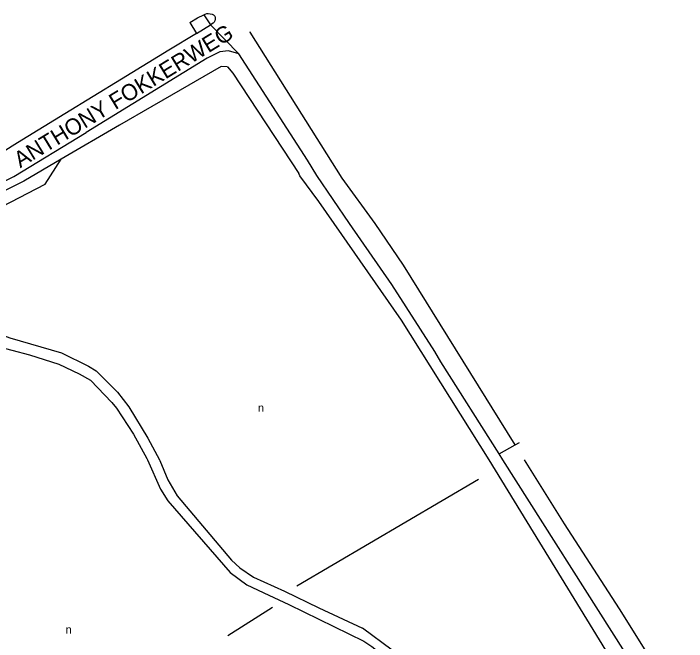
# Model space of a CAD drawing. Extents: x 158142 to 159655, y 385262 to 387204.
# Drawn here: x 158722.6 to 159056.3, y 386892.7 to 387204.1 of the extents above; entities that cross this region are included whole.
import ezdxf

# ---------------------------------------------------------------- set-up
doc = ezdxf.new("R2010")
doc.units = 0
for name, color, linetype in [('BLT_Basislijn', 7, 'Continuous'), ('BLT_Centroide', 7, 'Continuous'), ('BLT_Straatnaam_hoofdweg', 7, 'Continuous'), ('BLT_Vlakafsluiter', 7, 'Continuous')]:
    doc.layers.add(name, color=color, linetype=linetype)

msp = doc.modelspace()

# ---------------------------------------------------------------- linework, layer by layer
at = {"layer": 'BLT_Basislijn'}
for p, q in [((158816.98, 387203.45), (158820.21, 387198.39)), ((158810.01, 387199.61), (158813.28, 387194.17)), ((158813.28, 387194.17), (158820.21, 387198.39)), ((158796.72, 387161.14), (158791.2, 387157.97)), ((158747.97, 387154.24), (158724.65, 387139.9)), ((158863.12, 386920.32), (158953.18, 386973.15)), ((158828.89, 386895.71), (158851.1, 386909.64))]:
    msp.add_line(p, q, dxfattribs=at)
for points in [[(158810.01, 387199.61), (158813.77, 387201.92), (158816.98, 387203.45)], [(158816.98, 387203.45), (158817.67, 387203.77), (158818.39, 387204.08), (158819.17, 387204.08), (158821.12, 387203.68), (158821.81, 387203.39), (158822.38, 387202.81), (158822.65, 387202.12), (158822.65, 387201.31), (158822.44, 387200.42), (158822.11, 387199.72), (158821.57, 387199.19), (158820.21, 387198.39)], [(158813.28, 387194.17), (158799.69, 387185.88), (158776.2, 387171.42), (158747.97, 387154.24)], [(158971.41, 386990.24), (158916.01, 387079.26), (158902, 387100), (158885.59, 387122.48), (158840.02, 387194.82), (158840.05, 387195.16)], [(158834.41, 387184.11), (158829.27, 387185.49), (158824.86, 387185.13), (158818.64, 387181.87), (158758.56, 387145.1)], [(158963.45, 386985.65), (158934.46, 387031.39), (158931.54, 387036.42), (158910.12, 387069.72), (158889.28, 387100), (158873.07, 387123.67), (158868.42, 387131.41), (158834.41, 387184.11)], [(158828.56, 387177.67), (158825.65, 387177.76), (158796.72, 387161.14)], [(158828.56, 387177.67), (158828.76, 387177.61), (158831.4, 387174.54), (158864.09, 387124.71)], [(158791.2, 387157.97), (158775.15, 387148.76)], [(158775.15, 387148.76), (158746.24, 387131.78)], [(158656.08, 387088.12), (158665.09, 387093.2), (158682.14, 387102.8), (158697.48, 387110.9), (158722.77, 387123.25), (158758.56, 387145.1)], [(158724.65, 387139.9), (158717.53, 387135.44), (158691.44, 387119.47), (158680.62, 387110.78), (158678.6, 387109.21), (158673.07, 387105.98)], [(158601.87, 387043.7), (158663.51, 387076.57), (158703.82, 387101.71), (158706.29, 387105.85), (158716.99, 387108.3), (158738.31, 387119.52), (158746.24, 387131.78)], [(158746.24, 387131.78), (158727.74, 387120.92), (158711.33, 387112.82), (158635.07, 387069.15)], [(158958.42, 386982.75), (158915.05, 387052.06), (158881.53, 387100), (158873.95, 387110.89), (158864.56, 387123.63), (158864.09, 387124.71)], [(158689.96, 387059.86), (158690.74, 387056.94), (158693.14, 387055.45), (158700.11, 387051.72), (158707.9, 387047.99), (158720.81, 387043.24), (158746.32, 387035.84), (158759.77, 387029.16), (158763.61, 387026.95), (158774.11, 387016.37)], [(158685.14, 386982.75), (158687.96, 387003.81), (158689.75, 387042.71), (158690.33, 387044.22), (158691.93, 387045.94), (158693.02, 387046.57), (158696.92, 387046.72), (158702.97, 387043.35), (158712.86, 387039.5), (158730.6, 387034.84), (158745.14, 387030.27), (158755.08, 387025.45), (158760.74, 387022.19), (158771.37, 387011.13)], [(158774.11, 387016.37), (158779.72, 387009.05), (158789.26, 386993.54), (158794.96, 386982.75)], [(158771.37, 387011.13), (158773.61, 387008.33), (158782.1, 386995.45), (158788.78, 386983.36), (158789.05, 386982.75)], [(158965.29, 386982.75), (158963.45, 386985.65)], [(158789.05, 386982.75), (158795.46, 386968.16), (158799.18, 386962.38), (158830.05, 386926.87), (158838.27, 386920.81), (158849.21, 386915.61)], [(158794.96, 386982.75), (158795.14, 386982.41), (158799.16, 386972.86), (158803.82, 386964.96), (158830.77, 386933.07), (158834.86, 386929.24), (158841.64, 386924.58), (158857.01, 386917.58)], [(159103.65, 386742.39), (159099.94, 386748.36), (159098.83, 386750), (159091.4, 386761.9), (159082.06, 386777.82), (159078.59, 386786.94), (159064.74, 386809.3), (158958.42, 386982.75)], [(159083.22, 386795.27), (159074.66, 386809.4), (159063.45, 386827.49), (159040.75, 386863.13), (159025.87, 386887.16), (158965.29, 386982.75)], [(159089.59, 386802.28), (159073.79, 386827.75), (159023.04, 386908.93), (158995.81, 386951.04), (158976.07, 386982.75)], [(158849.21, 386915.61), (158859.17, 386910.94), (158896.27, 386892.92)], [(158857.01, 386917.58), (158873.93, 386909.3)], [(158873.93, 386909.3), (158895.73, 386899.33)], [(158929.94, 386871.18), (158915.21, 386884.4), (158910.37, 386888.39), (158895.73, 386899.33)], [(158896.27, 386892.92), (158900.34, 386890.22), (158909.81, 386882.69), (158919.27, 386874.47), (158929.05, 386864.56), (158932.64, 386858.61), (158944.48, 386824.01), (158945.66, 386818.41), (158945.43, 386809.38), (158943.15, 386802.81), (158940.34, 386797.93), (158934.04, 386791.34), (158913.14, 386778.2)]]:
    msp.add_lwpolyline(points, dxfattribs=at)
at = {"layer": 'BLT_Vlakafsluiter'}
for p, q in [((158820.21, 387198.39), (158834.41, 387184.11)), ((158963.45, 386985.65), (158971.41, 386990.24)), ((158971.41, 386990.24), (158973.44, 386991.41))]:
    msp.add_line(p, q, dxfattribs=at)

# ---------------------------------------------------------------- texts
at = {"layer": 'BLT_Centroide'}
for p in [(158843.82, 387006.58), (158748.45, 386896.6)]:
    msp.add_text('n', height=4, dxfattribs=at).set_placement(p)
at = {"layer": 'BLT_Straatnaam_hoofdweg'}
msp.add_text('ANTHONY FOKKERWEG', height=8, rotation=31.4388, dxfattribs=at).set_placement((158725.93, 387127.29))

doc.saveas('drawing.dxf')
